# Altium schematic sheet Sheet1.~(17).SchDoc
size A; SheetNumber: 1; SheetTotal: 1
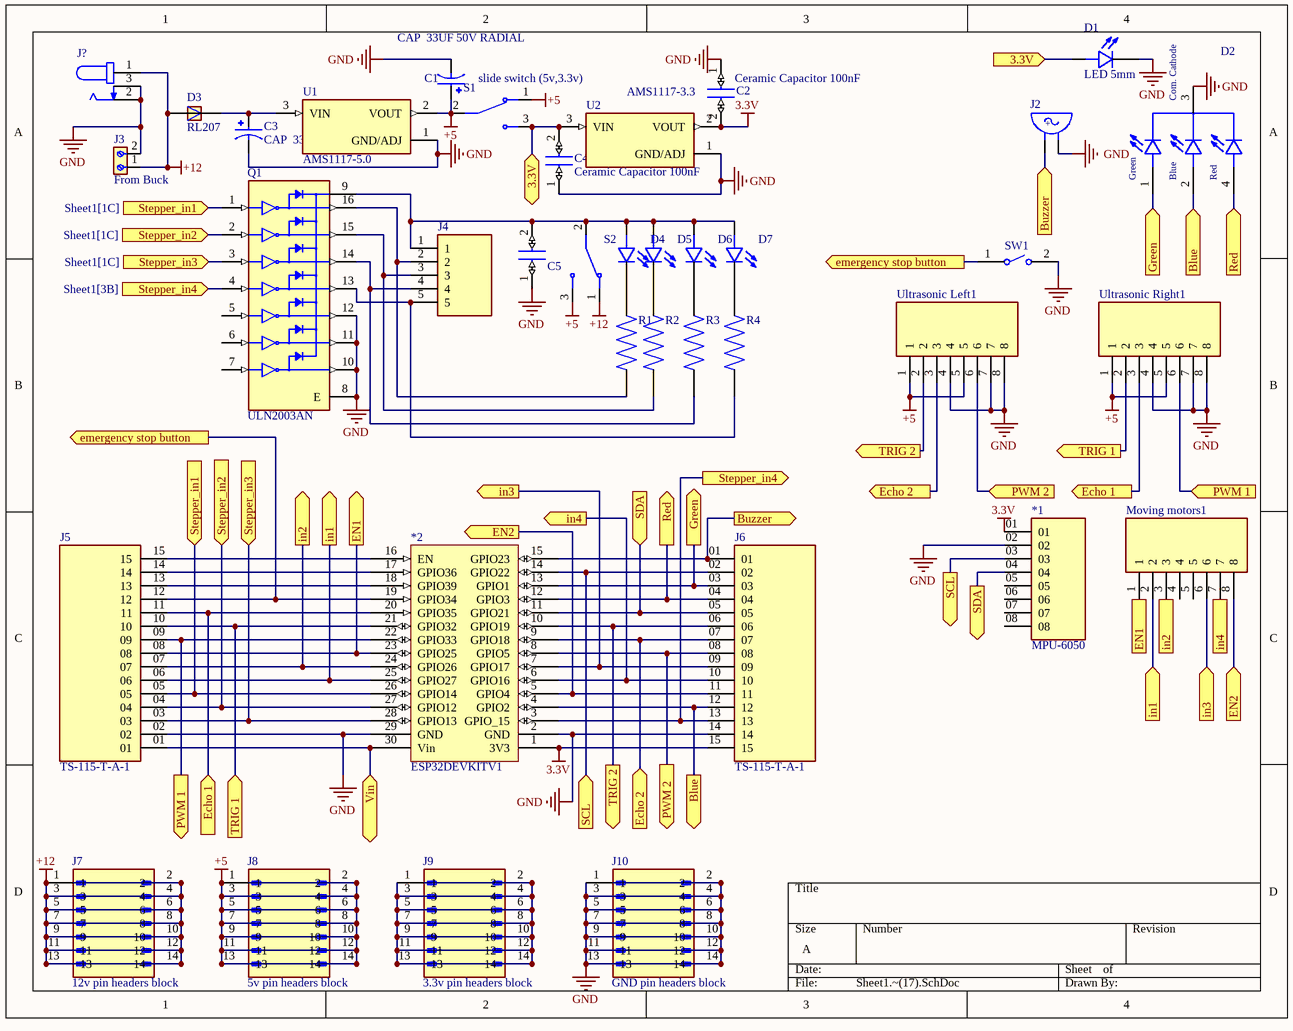
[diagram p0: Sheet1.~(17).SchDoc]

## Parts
*1  MPU-6050  [MPU-6050]
*2  ESP32DEVKITV1  [ESP32DEVKITV1]
C1  CAP  33UF 50V RADIAL  [CAP  33UF 50V RADIAL]
C2  Ceramic Capacitor 100nF  [C320C]
C3  CAP  33UF 50V RADIAL  [CAP  33UF 50V RADIAL]
C4  Ceramic Capacitor 100nF  [C320C]
C5  Ceramic Capacitor 100nF  [C320C]  (value not drawn)
D1  LED 5mm  [LED 5mm]
D2  common cathode  [LED RGB 5mm]  (value not drawn)
D3  RL207  [DIOAD1300W80L670D310]
D4  LED 5mm  [LED 5mm]  (value not drawn)
D5  LED 5mm  [LED 5mm]  (value not drawn)
D6  LED 5mm  [LED 5mm]  (value not drawn)
D7  LED 5mm  [LED 5mm]  (value not drawn)
J2  WST-1205S  [WST-1205S]  (value not drawn)
J3  From Buck  [691213510002]
J4  Pin hreader 5 pins  [Pin hreader 5 pins]  (value not drawn)
J5  TS-115-T-A-1  [SAMTEC_TS-115-T-A-1]
J6  TS-115-T-A-1  [SAMTEC_TS-115-T-A-1]
J7  12v pin headers block  [AMPHENOL_52601-S14-4LF]
J8  5v pin headers block  [AMPHENOL_52601-S14-4LF]
J9  3.3v pin headers block  [AMPHENOL_52601-S14-4LF]
J10  GND pin headers block  [AMPHENOL_52601-S14-4LF]
J?  DC Power Jack Female Socket  [DC Power Jack Female Socket]  (value not drawn)
Moving_motors1  Pin header female block 8 pin  [Pin header female block 8 pin]  (value not drawn)
Q1  ULN2003AN  [DIP794W45P254L1969H508Q16]
R1  Resistor  [RESAD700W45L350D185]  (value not drawn)
R2  Resistor  [RESAD700W45L350D185]  (value not drawn)
R3  Resistor  [RESAD700W45L350D185]  (value not drawn)
R4  Resistor  [RESAD700W45L350D185]  (value not drawn)
S1  slide switch (5v,3.3v)  [SW_EG1206]
S2  Slide switch  [Slide switch]  (value not drawn)
SW1  FSM8JRT  [TE_FSM8JRT]  (value not drawn)
U1  AMS1117-5.0  [SOT229P700X180-4N]
U2  AMS1117-3.3  [SOT229P700X180-4N]
Ultrasonic_Left1  Pin header female block 8 pin  [Pin header female block 8 pin]  (value not drawn)
Ultrasonic_Right1  Pin header female block 8 pin  [Pin header female block 8 pin]  (value not drawn)

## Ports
3.3V (bidir, see Sheet1[4A]), 3.3V (in, see Sheet1[2A]), Blue (in, see Sheet1[3D]), Blue (out, see Sheet1[4B]), Buzzer (in, see Sheet1[3C]), Buzzer (out, see Sheet1[4A]), Echo 1 (in, see Sheet1[4B]), Echo 1 (out, see Sheet1[1D]), Echo 2 (in, see Sheet1[3B]), Echo 2 (out, see Sheet1[2D]), emergency stop button (out, see Sheet1[1B]), emergency stop button (out, see Sheet1[3B]), EN1 (in, see Sheet1[2C]), EN1 (out, see Sheet1[4C]), EN2 (in, see Sheet1[2C]), EN2 (out, see Sheet1[4C]), Green (in, see Sheet1[3C]), Green (out, see Sheet1[4B]), in1 (in, see Sheet1[2C]), in1 (out, see Sheet1[4C]), in2 (in, see Sheet1[1C]), in2 (out, see Sheet1[4C]), in3 (in, see Sheet1[2B]), in3 (out, see Sheet1[4C]), in4 (in, see Sheet1[2C]), in4 (out, see Sheet1[4C]), PWM 1 (in, see Sheet1[1D]), PWM 1 (out, see Sheet1[4B]), PWM 2 (in, see Sheet1[3D]), PWM 2 (out, see Sheet1[4B]), Red (in, see Sheet1[3C]), Red (out, see Sheet1[4B]), SCL (in, see Sheet1[3C]), SCL (out, see Sheet1[2D]), SDA (in, see Sheet1[4C]), SDA (out, see Sheet1[2C]), Stepper_in1 (in, see Sheet1[1A]), Stepper_in1 (in, see Sheet1[1C]), Stepper_in2 (in, see Sheet1[1A]), Stepper_in2 (in, see Sheet1[1C]), Stepper_in3 (in, see Sheet1[1B]), Stepper_in3 (in, see Sheet1[1C]), Stepper_in4 (in, see Sheet1[3B]), Stepper_in4 (out, see Sheet1[1B]), TRIG 1 (in, see Sheet1[4B]), TRIG 1 (out, see Sheet1[1D]), TRIG 2 (out, see Sheet1[2D]), TRIG 2 (out, see Sheet1[3B]), Vin (bidir)

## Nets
3.3V: *1.01 *2.1(3V3) C2.2 J6.15 U2.2(VOUT)
 GND: *1.02 *2.2(GND) *2.29(GND) C1.N C2.1 C3.N C4.1 C5.1 D1.C D2.3(Com._Cathode) J2.NEG J3.2 J5.02 J6.14 J10.1 J10.2 J10.3 J10.4 J10.5 J10.6 J10.7 J10.8 J10.9 J10.10 J10.11 J10.12 J10.13 J10.14 J?.2 J?.3 Q1.8(E) Q1.10(7C) Q1.11(6C) Q1.12(5C) SW1.2 U1.1(GND/ADJ) U2.1(GND/ADJ) Ultrasonic_Left1.4 Ultrasonic_Left1.7 Ultrasonic_Left1.8 Ultrasonic_Right1.4 Ultrasonic_Right1.7 Ultrasonic_Right1.8  [also labelled GND]
+5: C1.P J8.1 J8.2 J8.3 J8.4 J8.5 J8.6 J8.7 J8.8 J8.9 J8.10 J8.11 J8.12 J8.13 J8.14 S1.1 S1.2 S2.3 U1.2(VOUT) Ultrasonic_Left1.1 Ultrasonic_Left1.5 Ultrasonic_Right1.1 Ultrasonic_Right1.5
+12: D3.A J3.1 J7.1 J7.2 J7.3 J7.4 J7.5 J7.6 J7.7 J7.8 J7.9 J7.10 J7.11 J7.12 J7.13 J7.14 J?.1 S2.1
3.3V: C4.2 D1.A S1.3 U2.3(VIN) ; port 3.3V  [a separate net that carries the same name]
Blue: *2.4(GPIO2) D2.2(BLUE) J6.12 ; port Blue
Buzzer: *2.15(GPIO23) J2.POS J6.01 ; port Buzzer
Echo 1: *2.20(GPIO35) J5.11 Ultrasonic_Right1.3 ; port Echo 1
Echo 2: *2.9(GPIO18) J6.07 Ultrasonic_Left1.3 ; port Echo 2
emergency stop button: *2.19(GPIO34) J5.12 SW1.1 ; port emergency stop button
EN1: *2.23(GPIO25) J5.08 Moving_motors1.1 ; port EN1
EN2: *2.5(GPIO4) J6.11 Moving_motors1.8 ; port EN2
Green: *2.13(GPIO1) D2.1(Green) J6.03 ; port Green
in1: *2.25(GPIO27) J5.06 Moving_motors1.2 ; port in1
in2: *2.24(GPIO26) J5.07 Moving_motors1.3 ; port in2
in3: *2.7(GPIO17) J6.09 Moving_motors1.6 ; port in3
in4: *2.6(GPIO16) J6.10 Moving_motors1.7 ; port in4
PWM 1: *2.22(GPIO33) J5.09 Ultrasonic_Right1.6 ; port PWM 1
PWM 2: *2.8(GPIO5) J6.08 Ultrasonic_Left1.6 ; port PWM 2
Red: *2.12(GPIO3) D2.4(Red) J6.04 ; port Red
SCL: *1.03 *2.14(GPIO22) J6.02 ; port SCL
SDA: *1.04 *2.11(GPIO21) J6.05 ; port SDA
Stepper_in1: *2.26(GPIO14) J5.05 Q1.1(1B) ; port Stepper_in1
Stepper_in2: *2.27(GPIO12) J5.04 Q1.2(2B) ; port Stepper_in2
Stepper_in3: *2.28(GPIO13) J5.03 Q1.3(3B) ; port Stepper_in3
Stepper_in4: *2.3(GPIO_15) J6.13 Q1.4(4B) ; port Stepper_in4
TRIG 1: *2.21(GPIO32) J5.10 Ultrasonic_Right1.2 ; port TRIG 1
TRIG 2: *2.10(GPIO19) J6.06 Ultrasonic_Left1.2 ; port TRIG 2
Vin: *2.30(Vin) J5.01 ; port Vin
Net*2_16: *2.16(EN) J5.15
Net*2_17: *2.17(GPIO36) J5.14
Net*2_18: *2.18(GPIO39) J5.13
NetC3_P: C3.P D3.C U1.3(VIN)
NetC5_2: C5.2 D4.A D5.A D6.A D7.A J4.1 Q1.9(COM) S2.2
NetD4_C: D4.C R1.1
NetD5_C: D5.C R2.1
NetD6_C: D6.C R3.1
NetD7_C: D7.C R4.1
NetJ4_2: J4.2 Q1.16(1C) R1.2
NetJ4_3: J4.3 Q1.15(2C) R2.2
NetJ4_4: J4.4 Q1.14(3C) R3.2
NetJ4_5: J4.5 Q1.13(4C) R4.2
NetJ9_1: J9.1 J9.2 J9.3 J9.4 J9.5 J9.6 J9.7 J9.8 J9.9 J9.10 J9.11 J9.12 J9.13 J9.14

Not connected (* = marked no-connect by the designer): *1 05 06 07 08; Moving_motors1 4 5; Q1 5(5B) 6(6B) 7(7B)

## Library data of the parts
C1 C3 = CAP  33UF 50V RADIAL: NHG-A; MF: {'manufacturer': u'Panasonic'}; MP: ECA1HHG330I
C2 C4 C5 = Ceramic Capacitor 100nF: 0.1ÂµF Â±20% 50V Ceramic Capacitor Z5U Radial; MF: KEMET; MP: C320C104M5U5TA
D1 D4-D7 = LED 5mm: Red 623nm LED Indication - Discrete 1.9V Radial; MF: {'manufacturer': u'Wurth Elektronik'}; MP: 151054RS03000
D2 = LED RGB 5mm: MF: {'manufacturer': u'Kingbright'}; MP: WP154A4SUREQBFZGC
D3 = RL207: Semiconductors and Actives, Power Diodes, Discretes (diodes, transistors, thyristors ...), Diodes; MF: {'manufacturer': u'Diodes Inc.'}
J2 = WST-1205S: BUZZER 2.3KHZ 4-6VDC; MF: {'manufacturer': u'Soberton Inc.'}
J3 = Terminal Block: 2 Position Wire to Board Terminal Block Horizontal with Board 0.200 (5.08mm) Through Hole; MF: Wurth Electronics
J4 = Pin hreader 5 pins: MF: {'manufacturer': u'TE Connectivity'}; MP: 2355181-5
J5 J6 = TS-115-T-A-1: MF: {'manufacturer': u'Samtec'}
J7-J10 = 52601-S14-4LF: MF: {'manufacturer': u'Amphenol ICC (FCI)'}
J? = DC Power Jack Female Socket: 2.0 mm Center Pin, 2.5 A, Right Angle, Through Hole, Dc Power Jack Connector; MF: {'manufacturer': u'CUI Devices'}; MP: PJ-002A
Moving_motors1 Ultrasonic_Left1 Ultrasonic_Right1 = Pin header female block 8 pin: MF: {'manufacturer': u'TE Connectivity'}; MP: 5-534998-4
Q1 = ULN2003AN: MF: {'manufacturer': u'Texas Instruments'}
R1-R4 = Resistor: CFR16 5% 10K; MF: {'manufacturer': u'TE Connectivity'}; MP: 2-1623927-3
S1 = EG1206: MF: {'manufacturer': u'E-Switch'}
S2 = Slide switch: MF: {'manufacturer': u'E-Switch'}; MP: EG1206
SW1 = FSM8JRT: Tactile Switches PUSHBUTTON SWITCH TACT; MF: {'manufacturer': u'TE Connectivity'}
U1 = AMS1117-5.0: MF: {'manufacturer': u'Advanced Monolithic Systems'}
U2 = AMS1117-3.3: MF: {'manufacturer': u'Advanced Monolithic Systems'}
